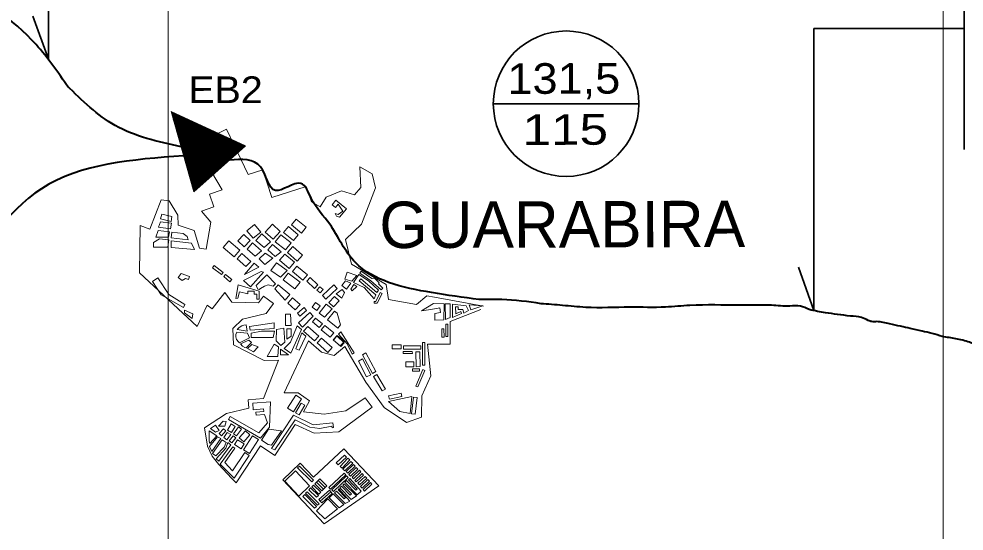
# Model space of a CAD drawing. Extents: x -4 to 42046, y -3 to 29697.
# Drawn here: x 25194 to 27137, y 13596 to 14650 of the extents above; entities that cross this region are included whole.
import ezdxf
from ezdxf.enums import TextEntityAlignment as Align

# ---------------------------------------------------------------- set-up
doc = ezdxf.new("R2010")
doc.units = 0
doc.header["$LTSCALE"] = 32
doc.linetypes.add('DOT_DASHED', pattern=[7.7, 5, -1.2, 0.3, -1.2])
doc.linetypes.add('LONG_DASHED', pattern=[7.5, 6, -1.5])
for name, color, linetype, lineweight in [('1', 7, 'DOT_DASHED', 13), ('4', 7, 'Continuous', 13), ('5', 7, 'LONG_DASHED', 25), ('6', 7, 'Continuous', 40), ('63', 7, 'Continuous', 25), ('8', 7, 'Continuous', 35), ('9', 7, 'Continuous', 40)]:
    doc.layers.add(name, color=color, linetype=linetype, lineweight=lineweight)

msp = doc.modelspace()

# ---------------------------------------------------------------- linework, layer by layer
at = {"layer": '1', "linetype": 'Continuous'}
for p, q in [((25812.94, 14263.25), (25825.13, 14283.07)), ((25560.17, 14017.54), (25581.02, 14061.22)), ((25620.21, 13778.69), (25611.92, 13783.96))]:
    msp.add_line(p, q, dxfattribs=at)
for points in [[(25812.94, 14263.25), (25795.01, 14273.56), (25784.55, 14305.56), (25713.77, 14282.48), (25695.04, 14339.79), (25665.34, 14330.1), (25620.28, 14422.83), (25591.46, 14408.86), (25599.43, 14392.45), (25565.66, 14376.08), (25611.79, 14298.18), (25585.86, 14289.27), (25594.78, 14263.37), (25568.86, 14254.46), (25588.24, 14231.85), (25579.02, 14176.06), (25564.79, 14178.41), (25554.06, 14214.64), (25520.9, 14225.58), (25520.84, 14246.56), (25502.53, 14275.77), (25485.96, 14277.93), (25462.95, 14217.68), (25443.25, 14225.19), (25441.69, 14127.62), (25560.17, 14017.54)], [(26148.92, 14058.88), (26148.92, 14058.88), (26048.07, 14077.42), (26032.53, 14080.28), (26011.37, 14062.24), (25953.87, 14072.43), (25949.07, 14103.5), (25877.35, 14145.68), (25864.95, 14196.52), (25897.83, 14227.71), (25926.81, 14302.22), (25920.13, 14331.4), (25894.65, 14345.46), (25896.66, 14303.07), (25883.52, 14287.96), (25857.12, 14296.36), (25825.13, 14283.07)], [(25581.02, 14061.22), (25590.98, 14053.52), (25617.11, 14087.25), (25631.25, 14067.45), (25686.46, 14065.95), (25696.91, 14079.79), (25717.37, 14064.37), (25701.93, 14043.93), (25653.44, 14032.18), (25633.62, 14012.79), (25634.82, 13979.67), (25697.86, 13947.28), (25727.12, 13947.92), (25696.43, 13868.87), (25664.97, 13866.57), (25666.22, 13849.5), (25620.25, 13838.05), (25575.17, 13808.52), (25581.73, 13771.25), (25591.08, 13750.31), (25604.71, 13733.37), (25631.17, 13705.24), (25640.11, 13695.74), (25690.27, 13771.5), (25719.59, 13752.14), (25761.78, 13815.88), (25801.08, 13797.81), (25851.69, 13800.18), (25920.05, 13851.27), (25905.78, 13870.33), (25865.56, 13843.88), (25821.08, 13836.79), (25778.79, 13841.95), (25791.24, 13863.96), (25767.55, 13880.86), (25739.18, 13880.49), (25788.92, 13987.72), (25815.69, 13964.72), (25842.14, 13957.56), (25863.5, 13975.98), (25906.83, 13902.69), (25944.81, 13850.79), (25990.45, 13819.41), (26021.17, 13830.68), (26022.09, 13874.72), (26040.49, 13916.01), (26034.01, 13980.64), (26080.48, 13981.13), (26080, 14027.56), (26143.18, 14051.91)], [(25611.92, 13783.96), (25591.82, 13756.1), (25598.33, 13751.41), (25615.94, 13768.75), (25620.21, 13778.69)]]:
    msp.add_lwpolyline(points, dxfattribs=at)
for points in [[(25867.39, 14259.08), (25845.32, 14277.03), (25837.48, 14267.4), (25844.3, 14261.86), (25849.85, 14268.67), (25859.73, 14254.72), (25849.98, 14247.83), (25844.07, 14250), (25846.75, 14244.34), (25853.1, 14242.02)], [(25506.6, 14233.54), (25485.02, 14238.48), (25487.33, 14248.57), (25508.43, 14243.74)], [(25480.69, 14221.59), (25485.04, 14232.85), (25507.23, 14229.79), (25505.65, 14218.37)], [(25675.66, 14198.61), (25662.7, 14214.16), (25678.25, 14227.11), (25691.22, 14211.57)], [(25716.33, 14196.83), (25700.32, 14211.61), (25715.11, 14227.59), (25731.11, 14212.82)], [(25758.13, 14193.92), (25737.94, 14210.58), (25747.89, 14222.6), (25768.08, 14205.94)], [(25774.43, 14209.55), (25753.86, 14226.21), (25763.45, 14238.02), (25784.02, 14221.36)], [(25501.07, 14201.02), (25475.13, 14200.95), (25480.09, 14214.4), (25503.53, 14211.97)], [(25541.71, 14195.52), (25506.7, 14199.48), (25508.02, 14211.18), (25531.24, 14208.55), (25539.5, 14202.7)], [(25656.71, 14181.08), (25643.76, 14193.58), (25656.27, 14206.52), (25669.23, 14194.02)], [(25697.76, 14179.68), (25680.99, 14194.45), (25692.86, 14207.88), (25711.21, 14191.71)], [(25741.85, 14174.87), (25720.9, 14191.53), (25732.44, 14206.01), (25753.39, 14189.35)], [(25499.88, 14180.71), (25470.5, 14180.62), (25470.48, 14190), (25482.95, 14197.85), (25502.02, 14195.72)], [(25506.76, 14179.48), (25554.89, 14175.56), (25548.29, 14188.98), (25507.03, 14193.54)], [(25636.64, 14160.5), (25613.78, 14179.81), (25625.23, 14193.33), (25648.09, 14174.02)], [(25679.19, 14161.76), (25662.81, 14176.16), (25674.11, 14188.99), (25692.36, 14172.95)], [(25720.61, 14161.51), (25705.37, 14174.76), (25715.38, 14186.24), (25733.25, 14170.7)], [(25660.64, 14140.43), (25642.35, 14156.72), (25651.99, 14167.52), (25670.27, 14151.23)], [(25699.38, 14144.73), (25687.95, 14156.47), (25699.71, 14167.89), (25715.68, 14157.69)], [(25749.56, 14136.51), (25729.75, 14153.56), (25740.75, 14166.31), (25760.56, 14149.27)], [(25765.48, 14151.38), (25745.67, 14169.56), (25756.99, 14181.88), (25776.81, 14163.7)], [(25687.24, 14138.99), (25677.33, 14147.32), (25657.86, 14124.22)], [(25731.38, 14118.6), (25711.96, 14132.22), (25723.23, 14148.25), (25745.56, 14132.58)], [(25529.46, 14112.05), (25521.31, 14117.96), (25527.23, 14126.09), (25544.43, 14120.22), (25542.28, 14113.94), (25536, 14116.09)], [(25613.78, 14128.55), (25594.99, 14142.55), (25591.73, 14138.2), (25610.53, 14124.19)], [(25631.32, 14113.6), (25618.79, 14124.5), (25614.77, 14119.89), (25627.31, 14108.99)], [(25696.77, 14128.76), (25669.88, 14098.66), (25655.31, 14111.64), (25691.82, 14130.64)], [(25761.09, 14094.37), (25736.72, 14112.92), (25747.38, 14126.9), (25771.75, 14108.35)], [(25777.76, 14112.66), (25756.04, 14130.45), (25765.09, 14141.47), (25786.8, 14123.68)], [(25877.95, 14110.3), (25864.03, 14114.8), (25868.53, 14128.7), (25888.43, 14122.27)], [(25938.44, 14092.32), (25917.1, 14111.27), (25894.64, 14126.81), (25897.51, 14130.95), (25918.99, 14116.1), (25926.17, 14115.27), (25934.71, 14107.06), (25932.73, 14105.01), (25941.95, 14096.14)], [(25532.12, 14056.12), (25486.42, 14082.55), (25468.21, 14109.99), (25479.21, 14117.27), (25501.97, 14082.95), (25534.92, 14062.69)], [(25681.65, 14101.73), (25703.24, 14123.46), (25721.56, 14105.29), (25716.61, 14100.32), (25706.35, 14102.95), (25698.37, 14100.26), (25690.51, 14095.13), (25687.48, 14093.16), (25685.13, 14093.98)], [(25801.37, 14095.63), (25785.36, 14110.4), (25792.2, 14117.79), (25808.2, 14103.02)], [(25866.93, 14094.09), (25857.54, 14101.44), (25864.9, 14110.82), (25876.25, 14106.61)], [(25932.77, 14092.02), (25912.28, 14110.97), (25892.66, 14124.25), (25881.54, 14107.85), (25903.24, 14097.61), (25924.02, 14074.4), (25927.4, 14082.35), (25893.55, 14111.2), (25896.83, 14115.04), (25929.39, 14087.3)], [(25639.55, 14075.01), (25644.79, 14103.14), (25687.77, 14089.59), (25687.81, 14073.63), (25683.25, 14073.62), (25683.22, 14083.88), (25677.14, 14083.86), (25677.13, 14089.93), (25664.21, 14089.89), (25664.22, 14084.2), (25647.11, 14088.71), (25643.59, 14075.39)], [(25750.86, 14082.94), (25726.49, 14103.01), (25719.73, 14094.82), (25741.4, 14071.13)], [(25813.17, 14086.16), (25806.32, 14092.22), (25812.38, 14099.07), (25819.24, 14093.01)], [(25824.99, 14073.66), (25818.13, 14080.86), (25841.12, 14102.72), (25847.98, 14095.52)], [(25857.66, 14075.66), (25845.86, 14084.74), (25858.37, 14093.52), (25862.9, 14087.08)], [(25888.76, 14099.27), (25878.57, 14090.72), (25875.93, 14093.87), (25882.22, 14103.79)], [(25930.58, 14065.05), (25924.05, 14065.03), (25924.04, 14068.72), (25927.73, 14068.73), (25936.75, 14087.21), (25940.52, 14085.37)], [(25761.98, 14051.81), (25746.74, 14065.45), (25756.5, 14076.34), (25771.74, 14062.71)], [(25806.44, 14050.42), (25796.92, 14057.24), (25803.74, 14066.75), (25813.26, 14059.93)], [(25840.62, 14057.75), (25831.09, 14066.46), (25842.7, 14079.12), (25852.38, 14070.27)], [(25550, 14033.36), (25534.34, 14045.19), (25534.33, 14050.5), (25551.22, 14043.36)], [(25771.52, 14038.54), (25766.18, 14044.98), (25779.87, 14056.31), (25785.21, 14049.86)], [(25822.06, 14036.41), (25811.02, 14044.74), (25825.09, 14063.37), (25838.08, 14053.58)], [(25849.49, 14014.07), (25828.16, 14030.73), (25842.44, 14048.98), (25848.06, 14044.6), (25855.17, 14020.93)], [(26066.98, 14030.64), (26048.6, 14030.58), (26048.56, 14043.84), (26060.74, 14046.01), (26058.99, 14055.79), (26040.34, 14052.46), (26021.69, 14049.13), (26045.72, 14064.78), (26068.17, 14063.78)], [(26070.82, 14031.48), (26080.19, 14035.51), (26080.11, 14063.88), (26070.27, 14063.85)], [(26108.15, 14044.95), (26118.29, 14049.9), (26113.34, 14060.03), (26084.83, 14063.24), (26085.23, 14036.04), (26103.89, 14043.96), (26102.25, 14047.81), (26091.68, 14043.32), (26091.4, 14057.36), (26096.62, 14057.46), (26096.73, 14052.24), (26106.48, 14052.44)], [(26122.55, 14051.55), (26119.24, 14061.7), (26147.43, 14059.49)], [(25753.69, 14019), (25741.73, 14018.97), (25741.66, 14042.33), (25752.23, 14042.36)], [(25776.52, 14016.14), (25768.52, 14024.85), (25791.54, 14045.95), (25798.38, 14038.51)], [(25811.1, 14015.1), (25797.01, 14026.84), (25803.56, 14034.69), (25817.66, 14022.95)], [(25663.15, 14007.5), (25642.83, 14010.86), (25646.45, 14014.83), (25651.79, 14018.59), (25656.38, 14019.78), (25660.97, 14020.97)], [(25718.39, 14013.34), (25718.36, 14024.74), (25667.77, 14017.36), (25668.92, 14009.5)], [(25716.78, 13994.43), (25671.18, 13994.29), (25671.15, 14003.47), (25692.27, 14007.7), (25718.96, 14007.78)], [(25732.12, 13977.79), (25722.64, 13987.77), (25723.4, 14010.85), (25738.41, 14013.95), (25740.44, 13985.32)], [(25774.57, 14010.72), (25765.92, 14018.48), (25752.4, 13985.08), (25739.09, 13971.69), (25753.02, 13962.56)], [(25744.6, 13990.89), (25744.53, 14012.58), (25753.43, 14012.61), (25753.48, 13997.31)], [(25801.31, 13987.71), (25778.83, 14007.4), (25787.44, 14017.21), (25810.5, 13997.02)], [(25833.58, 13995.03), (25815.3, 14010.17), (25822.94, 14019.38), (25841.23, 14004.23)], [(26067.66, 13995.02), (26067.61, 14012.39), (26063.35, 14012.38), (26063.4, 13995.01)], [(26075.85, 13996.69), (26075.77, 14022.25), (26071.18, 14022.23), (26071.26, 13996.67)], [(25668.01, 13993.83), (25664.02, 14003.44), (25641.99, 14005.84), (25639.86, 14000.7), (25639.77, 13995.78), (25641.28, 13990.54), (25645.15, 13985.96), (25647.03, 13983.73)], [(25666.52, 13989.34), (25649.12, 13981.37), (25653.19, 13976.68), (25658.44, 13974.23), (25660.72, 13973.18), (25672.1, 13984.54)], [(25783.51, 13997.13), (25775.42, 14004.05), (25763.01, 13971.48), (25770.04, 13968.81)], [(25806.64, 13983.55), (25828.74, 13963.85), (25837.63, 13973.8), (25815.53, 13993.5)], [(25855.3, 13976.09), (25840.06, 13990.1), (25847.27, 13997.93), (25862.51, 13983.91)], [(25854.22, 13977.43), (25840.28, 13989.3), (25848.38, 13998.78), (25862.78, 13986.51)], [(25851.03, 14001.54), (25855.56, 14006.09), (25882.92, 13963.32), (25878.56, 13960.54), (25868.4, 13981.73)], [(25676.27, 13965.39), (25663.46, 13971.74), (25672.61, 13980.11), (25685.97, 13975.15)], [(25725.79, 13955.52), (25703.83, 13955.46), (25718.77, 13980.81), (25727.48, 13975.68)], [(25747.75, 13959.2), (25731.34, 13959.15), (25731.31, 13970.55)], [(25960.9, 13971.11), (25979.91, 13971.17), (25979.88, 13979.69), (25960.88, 13979.63)], [(25984.5, 13970.53), (25984.48, 13977.41), (26020.2, 13977.51), (26020.22, 13970.63)], [(26028.18, 13937.89), (26028.04, 13984.42), (26023.12, 13984.4), (26023.26, 13937.87)], [(25908.64, 13913.61), (25891.83, 13946), (25900.41, 13950.44), (25917.22, 13918.05)], [(25920.74, 13920.85), (25899.99, 13959.13), (25906.66, 13962.75), (25927.42, 13924.47)], [(25983.53, 13965.94), (26002.53, 13965.99), (26002.55, 13961.73), (25983.54, 13961.68)], [(26018.36, 13934.58), (26018.27, 13965.06), (26010.07, 13965.03), (26010.17, 13934.55)], [(25989.19, 13934.16), (26005.58, 13934.21), (26005.55, 13944.37), (25989.16, 13944.32)], [(25940.84, 13884.54), (25923.06, 13914.31), (25929.57, 13918.19), (25947.35, 13888.42)], [(26017.39, 13929.99), (26002.97, 13929.95), (26002.98, 13925.36), (26017.4, 13925.4)], [(26013.89, 13892.95), (26028.21, 13926.74), (26024.17, 13928.45), (26009.85, 13894.66)], [(25758, 13841.64), (25774.8, 13868.49), (25762.78, 13875.99), (25745.99, 13849.14)], [(25998, 13838.5), (25977.01, 13842.37), (25953.69, 13862.95), (26001.5, 13873.25)], [(25955.31, 13867.54), (25981.18, 13873.52), (25979.63, 13880.23), (25953.76, 13874.25)], [(26000.95, 13837.53), (26005.11, 13871.95), (26012.21, 13871.09), (26008.05, 13836.67)], [(25686.99, 13798.41), (25628.32, 13832.32), (25624.49, 13825.7), (25690.54, 13787.53), (25708.79, 13810.39), (25710.95, 13862.34), (25674.57, 13859.26), (25675.7, 13845.9), (25696.69, 13847.68), (25697.13, 13842.5), (25681.06, 13841.14), (25681.6, 13834.79), (25698.43, 13836.22), (25704.8, 13818.98)], [(25769.93, 13835.38), (25781.46, 13855.27), (25773.99, 13859.59), (25762.47, 13839.7)], [(25719.85, 13763.76), (25762.02, 13825.43), (25791.85, 13809.97), (25812.19, 13807.38), (25837.01, 13811.92), (25837.58, 13808.83), (25840.67, 13809.39), (25838.94, 13818.8), (25799.05, 13814.87), (25758.25, 13834.56), (25713.25, 13766.06)], [(25597.97, 13799.8), (25587.36, 13807.05), (25598.26, 13814.36), (25605.58, 13803.47)], [(25617.46, 13812.43), (25604.33, 13812.39), (25613.79, 13822.35), (25619.75, 13821.7)], [(25630.74, 13798.9), (25638.31, 13811.83), (25629.95, 13816.72), (25622.38, 13803.79)], [(25585.12, 13781.56), (25585.06, 13802.74), (25600.97, 13792.53), (25586.13, 13776.27)], [(25610.24, 13792.55), (25605.26, 13797.17), (25614.35, 13806.95), (25619.33, 13802.33)], [(25622.13, 13798.88), (25614.88, 13788.6), (25621.46, 13783.97), (25629.22, 13794.97)], [(25641.35, 13791.99), (25635.04, 13796.6), (25645.31, 13810.58), (25651.61, 13805.97)], [(25646.65, 13788.36), (25655.94, 13780.12), (25668.74, 13794.5), (25659.45, 13802.75)], [(25705.92, 13774.64), (25692.33, 13783.53), (25706.97, 13805.86), (25733.63, 13802.85), (25713.21, 13773.01)], [(25608.6, 13786.59), (25602.3, 13790.55), (25585.49, 13770.31), (25590.48, 13760.07)], [(25629.16, 13773.75), (25623.19, 13778.7), (25618.92, 13767.1), (25599.13, 13745.2), (25604.47, 13740.39)], [(25631.46, 13778.06), (25626.15, 13782.34), (25634.38, 13792.51), (25639.69, 13788.23)], [(25636.76, 13774.43), (25650.69, 13765.87), (25656.78, 13775.75), (25642.85, 13784.31)], [(25655.33, 13763.57), (25667.59, 13755.66), (25686.3, 13784.63), (25674.03, 13792.53)], [(25636.64, 13705.27), (25667.27, 13752.02), (25657.97, 13758.11), (25633.21, 13720.33), (25617.02, 13737.65), (25637.78, 13766.83), (25633.58, 13769.81), (25607.89, 13733.7)], [(25821.44, 13611.39), (25736.02, 13701.68), (25772.22, 13735.86), (25799.59, 13706.92), (25861.76, 13765.61), (25933.79, 13689.48)], [(25846.21, 13736.86), (25863.05, 13752.72), (25867.05, 13748.48), (25850.22, 13732.62)], [(25854.14, 13729.34), (25870.26, 13746.63), (25874.14, 13743.02), (25858.03, 13725.72)], [(25859.91, 13723.61), (25876.38, 13739.82), (25879.95, 13736.21), (25863.47, 13719.99)], [(25769.06, 13668.22), (25740.19, 13698.94), (25762.61, 13719.97), (25791.48, 13689.25)], [(25795.72, 13697.53), (25766.64, 13726.22), (25770.32, 13729.95), (25799.41, 13701.26)], [(25866.75, 13718.96), (25881.79, 13733.01), (25884.93, 13729.66), (25869.88, 13715.61)], [(25872.22, 13712.87), (25887.27, 13726.93), (25890.4, 13723.58), (25875.35, 13709.52)], [(25878.7, 13707.5), (25893.75, 13721.56), (25896.89, 13718.21), (25881.84, 13704.15)], [(25816.23, 13678.93), (25802.03, 13693.5), (25805.57, 13696.95), (25819.78, 13682.38)], [(25819.78, 13682.38), (25805.57, 13696.95), (25809.12, 13700.4), (25823.32, 13685.83)], [(25823.32, 13685.83), (25809.12, 13700.4), (25812.66, 13703.84), (25826.87, 13689.27)], [(25865.59, 13711.9), (25834.43, 13682.36), (25831.22, 13685.73), (25862.38, 13715.28)], [(25840.52, 13677.65), (25870.78, 13706.29), (25867.17, 13710.1), (25836.91, 13681.46)], [(25897.62, 13678.27), (25889.1, 13671.05), (25864.07, 13697.06), (25867.28, 13700.15), (25886.51, 13680.18), (25889.35, 13682.91), (25871.23, 13701.74), (25873.8, 13704.21)], [(25884.11, 13700.69), (25899.16, 13714.75), (25902.3, 13711.4), (25887.25, 13697.34)], [(25890.6, 13694.6), (25905.64, 13708.66), (25908.78, 13705.31), (25893.73, 13691.25)], [(25896.01, 13688.15), (25911.05, 13702.21), (25914.19, 13698.86), (25899.14, 13684.8)], [(25805.48, 13665.86), (25789.48, 13681.32), (25793.33, 13685.31), (25809.34, 13669.84)], [(25810.41, 13672.62), (25795.75, 13687.19), (25799.57, 13691.02), (25814.22, 13676.45)], [(25813.25, 13657.85), (25835, 13677.25), (25831.94, 13680.67), (25810.19, 13661.27)], [(25873.85, 13658.19), (25864.65, 13652.77), (25842.77, 13674.96), (25846.63, 13678.76), (25862.32, 13662.84), (25865.2, 13665.67), (25849.89, 13681.21), (25851.77, 13683.07)], [(25887.75, 13668.8), (25876.99, 13661.13), (25853.53, 13685.11), (25857.18, 13688.67), (25874.91, 13670.53), (25877.32, 13672.89), (25859.5, 13691.11), (25862.1, 13693.64)], [(25901.41, 13682.06), (25916.46, 13696.12), (25919.6, 13692.77), (25904.55, 13678.71)], [(25801.28, 13643.14), (25777.15, 13667.8), (25781.27, 13671.82), (25805.4, 13647.16)], [(25807.56, 13649.45), (25783.2, 13674.11), (25786.49, 13677.36), (25810.85, 13652.7)], [(25848.94, 13641.93), (25822.48, 13621.62), (25805.34, 13638.21), (25828.79, 13662.38)], [(25816.31, 13654.43), (25838.06, 13673.82), (25835, 13677.25), (25813.25, 13657.85)], [(25861.95, 13650.96), (25852.31, 13643.97), (25831.34, 13664.59), (25839.82, 13673.19)]]:
    msp.add_lwpolyline(points, close=True, dxfattribs=at)
at = {"layer": '4'}
for p, q in [((25506.88, 14458.12), (25507.6, 14458.84)), ((25507.51, 14455.92), (25509.54, 14457.95)), ((25508.13, 14453.72), (25511.48, 14457.06)), ((25508.76, 14451.51), (25513.42, 14456.17)), ((25509.38, 14449.31), (25515.35, 14455.28)), ((25510.01, 14447.11), (25517.29, 14454.39)), ((25510.63, 14444.9), (25519.23, 14453.5)), ((25511.26, 14442.7), (25521.17, 14452.61)), ((25511.88, 14440.49), (25523.11, 14451.72)), ((25512.51, 14438.29), (25525.05, 14450.83)), ((25513.13, 14436.09), (25526.98, 14449.94)), ((25513.76, 14433.88), (25528.92, 14449.05)), ((25514.38, 14431.68), (25530.86, 14448.16)), ((25515, 14429.48), (25532.8, 14447.27)), ((25515.63, 14427.27), (25534.74, 14446.38)), ((25516.25, 14425.07), (25536.68, 14445.49)), ((25516.88, 14422.86), (25538.62, 14444.6)), ((25517.5, 14420.66), (25540.55, 14443.71)), ((25518.13, 14418.46), (25542.49, 14442.82)), ((25518.75, 14416.25), (25544.43, 14441.93)), ((25519.38, 14414.05), (25546.37, 14441.04)), ((25520, 14411.85), (25548.31, 14440.15)), ((25520.63, 14409.64), (25550.25, 14439.26)), ((25521.25, 14407.44), (25552.18, 14438.37)), ((25521.88, 14405.23), (25554.12, 14437.48)), ((25522.5, 14403.03), (25556.06, 14436.59)), ((25523.13, 14400.83), (25558, 14435.7)), ((25523.75, 14398.62), (25559.94, 14434.81)), ((25524.38, 14396.42), (25561.88, 14433.92)), ((25525, 14394.22), (25563.82, 14433.03)), ((25525.62, 14392.01), (25565.75, 14432.14)), ((25526.25, 14389.81), (25567.69, 14431.25)), ((25526.87, 14387.61), (25569.63, 14430.36)), ((25527.5, 14385.4), (25571.57, 14429.47)), ((25528.12, 14383.2), (25573.51, 14428.58)), ((25528.75, 14380.99), (25575.45, 14427.69)), ((25529.37, 14378.79), (25577.38, 14426.8)), ((25530, 14376.59), (25579.32, 14425.91)), ((25530.62, 14374.38), (25581.26, 14425.02)), ((25531.25, 14372.18), (25583.2, 14424.13)), ((25531.87, 14369.98), (25585.14, 14423.24)), ((25532.5, 14367.77), (25587.08, 14422.35)), ((25533.12, 14365.57), (25589.02, 14421.46)), ((25533.75, 14363.36), (25590.95, 14420.57)), ((25534.37, 14361.16), (25592.89, 14419.68)), ((25535, 14358.96), (25594.83, 14418.79)), ((25535.62, 14356.75), (25596.77, 14417.9)), ((25536.24, 14354.55), (25598.71, 14417.01)), ((25536.87, 14352.35), (25600.65, 14416.12)), ((25537.49, 14350.14), (25602.58, 14415.23)), ((25538.12, 14347.94), (25604.52, 14414.34)), ((25538.74, 14345.73), (25606.46, 14413.45)), ((25539.37, 14343.53), (25608.4, 14412.56)), ((25539.99, 14341.33), (25610.34, 14411.67)), ((25540.62, 14339.12), (25612.28, 14410.78)), ((25541.24, 14336.92), (25614.22, 14409.89)), ((25541.87, 14334.72), (25616.15, 14409)), ((25542.49, 14332.51), (25618.09, 14408.11)), ((25543.12, 14330.31), (25620.03, 14407.22)), ((25543.74, 14328.1), (25621.97, 14406.33)), ((25544.37, 14325.9), (25623.91, 14405.44)), ((25544.99, 14323.7), (25625.85, 14404.55)), ((25545.62, 14321.49), (25627.78, 14403.66)), ((25546.24, 14319.29), (25629.72, 14402.77)), ((25546.86, 14317.09), (25631.66, 14401.88)), ((25547.49, 14314.88), (25633.6, 14400.99)), ((25548.11, 14312.68), (25635.54, 14400.1)), ((25548.74, 14310.47), (25637.48, 14399.21)), ((25549.36, 14308.27), (25639.42, 14398.32)), ((25549.99, 14306.07), (25641.35, 14397.43)), ((25550.61, 14303.86), (25643.29, 14396.54)), ((25551.24, 14301.66), (25645.23, 14395.65)), ((25551.86, 14299.46), (25647.17, 14394.76)), ((25552.49, 14297.25), (25649.11, 14393.87)), ((25553.11, 14295.05), (25651.05, 14392.98)), ((25570.07, 14309.18), (25652.98, 14392.09)), ((25596.23, 14332.51), (25654.92, 14391.2)), ((25622.38, 14355.84), (25656.86, 14390.31)), ((25648.54, 14379.16), (25658.8, 14389.42))]:
    msp.add_line(p, q, dxfattribs=at)
msp.add_lwpolyline([(25553.34, 14294.25), (25506.54, 14459.33), (25659.62, 14389.05)], close=True, dxfattribs=at)
at = {"layer": '6'}
for points in [[(25295.46, 14508.99), (25229.07, 14597.18), (25054.12, 14717.71), (24898.9, 14771.74), (24808.46, 14836.4)], [(25527.08, 14386.89), (25391.52, 14430.92), (25292.8, 14512.53)], [(25532.33, 14368.35), (25240.25, 14300.64), (25075.5, 14084.68), (25010.89, 13813.92), (25010.89, 13469.02), (24859.06, 13291.73), (24739.53, 13053.21), (24594.16, 12898.49)], [(26139.48, 14072.48), (26041.99, 14086.98), (25953.83, 14107.98), (25885.41, 14148.68), (25832.78, 14227.45), (25794.63, 14281.28), (25773.58, 14311.47), (25720.95, 14297.03), (25690.69, 14345.61), (25626.59, 14359.58)], [(26267.13, 14064.1), (26186.34, 14072.62), (26157.04, 14072.54), (26139.48, 14072.48)], [(28309.3, 13825.11), (28263.62, 13838.16), (28232.58, 13843.71), (28206.55, 13849.91), (28186.34, 13855.68), (28167.46, 13861.77), (28148.04, 13870.08), (28128.55, 13879.11), (28105.98, 13893.76), (28082.4, 13905.46), (28060.53, 13915.22), (28033.62, 13917.1), (28014.45, 13917.04), (28001.8, 13921.91), (27980.26, 13916.81), (27948.97, 13912.36), (27929.78, 13909.59), (27904.37, 13909.52), (27851.94, 13909.36), (27803.87, 13909.22), (27790.62, 13911.34), (27768.51, 13914.09), (27750.86, 13919.97), (27732.13, 13927.16), (27721.26, 13932.65), (27708.63, 13940.14), (27698.25, 13948.74), (27680.22, 13959.24), (27652.86, 13959.16), (27638.81, 13952.7), (27617.13, 13947.87), (27596.69, 13943.13), (27582.4, 13938.85), (27569.21, 13936.34), (27555.09, 13932.13), (27543.82, 13927.83), (27535.11, 13924.84), (27525.27, 13923.07), (27499.6, 13922.99), (27483.26, 13917.23), (27470.01, 13912.69), (27454.58, 13909.21), (27437.29, 13909.16), (27421.23, 13906.56), (27406.35, 13906.52), (27395.39, 13906.49), (27375.23, 13906.43), (27359.53, 13899.96), (27348.07, 13895.38), (27332.81, 13895.33), (27317.81, 13897.22), (27304.9, 13904.06), (27283.45, 13917.4), (27255.46, 13933.38), (27232.22, 13947.14), (27201.77, 13962.28), (27172.84, 13975.29), (27147.53, 13984.69), (27119.72, 13992.15), (27091.92, 13996.89), (27071.02, 14003.05), (27050.28, 14007.6), (27026.02, 14013.12), (27006.12, 14017.56), (26983.69, 14022.43), (26957.07, 14027.19), (26947.02, 14027.16), (26939.84, 14029.72), (26925.7, 14035.51), (26902.98, 14038.77), (26876.52, 14041.93), (26851.83, 14045.57), (26835.56, 14048.36), (26818.05, 14052.5), (26800.32, 14059.17), (26778.54, 14059.1), (26740.55, 14061.01), (26693.56, 14060.87), (26674.82, 14060.81), (26573.28, 14060.51), (26522.89, 14057.05), (26449.44, 14056.84), (26358.85, 14056.57), (26311.17, 14060.6), (26266.64, 14064.1)]]:
    msp.add_spline(points, degree=3, dxfattribs=at)
at = {"layer": '63', "lineweight": 13}
for p, q in [((25500.63, 10019.66), (25500.63, 18929.66)), ((27093.44, 10019.66), (27093.44, 18929.66))]:
    msp.add_line(p, q, dxfattribs=at)
at = {"layer": '8'}
msp.add_line((27136.68, 14381.6), (27136.68, 14854.98), dxfattribs=at)
for points in [[(25563.2, 15165.23), (25254.47, 15165.23), (25254.47, 14566.84), (25222.8, 14655.91)], [(27136.68, 14630.25), (26827.95, 14630.25), (26827.95, 14049.99), (26796.28, 14139.05)]]:
    msp.add_lwpolyline(points, dxfattribs=at)
at = {"layer": '9', "lineweight": 35}
msp.add_line((26169, 14475.52), (26468.27, 14475.52), dxfattribs=at)
msp.add_circle((26318.63, 14475.52), 149.63, dxfattribs=at)

# ---------------------------------------------------------------- texts
at = {"layer": '5', "width": 1.1}
msp.add_text('EB2', height=55, rotation=0.006, dxfattribs=at).set_placement((25618.58, 14476.78), align=Align.CENTER)
at = {"layer": '9'}
for s, width, p in [('131,5', 1.1, (26314.01, 14496.01)), ('115', 1.25, (26317.03, 14390.94))]:
    msp.add_text(s, height=63, rotation=0.17, dxfattribs=dict(at, width=width)).set_placement(p, align=Align.CENTER)
msp.add_text('GUARABIRA', height=95.46, rotation=0.17, dxfattribs=at).set_placement((25934.89, 14178.5))

doc.saveas('drawing.dxf')
